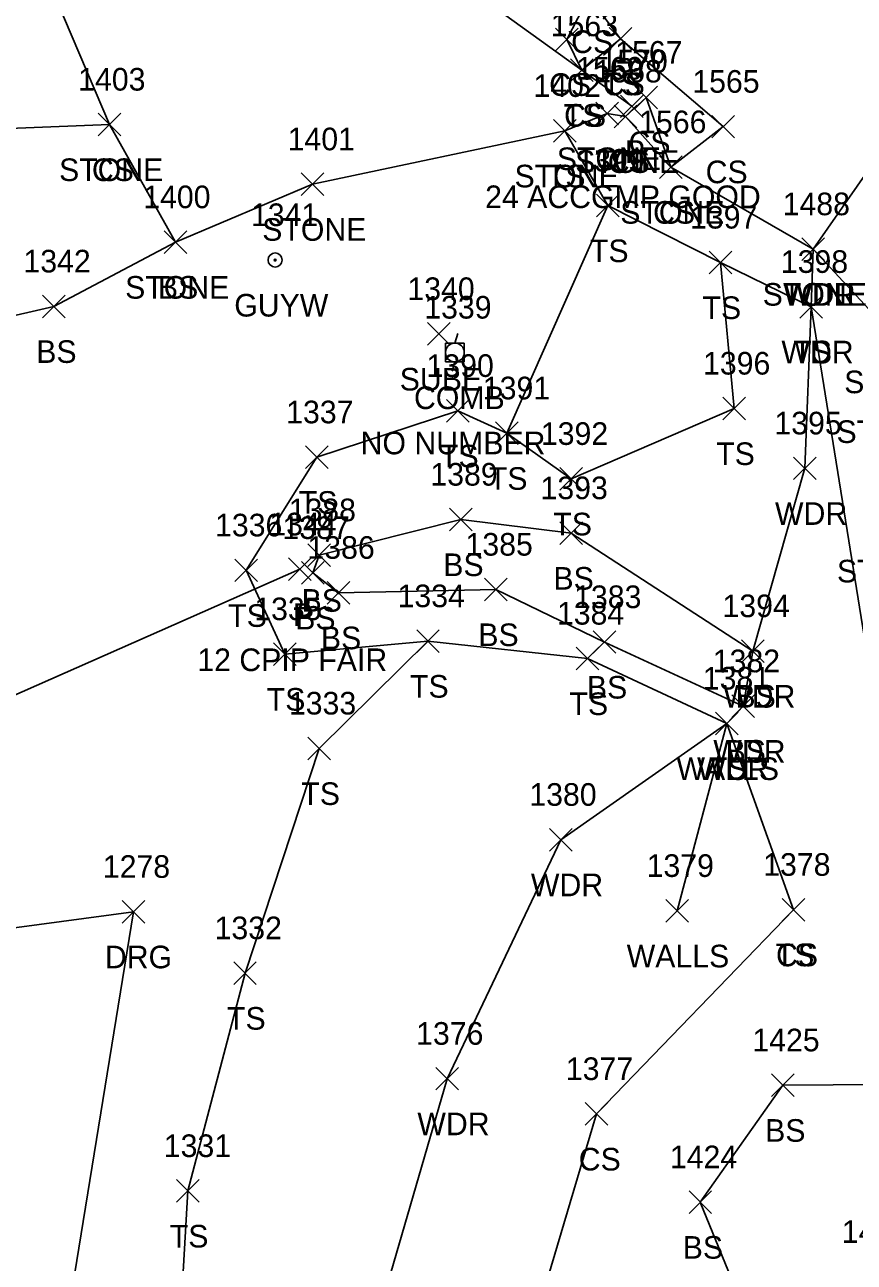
# Model space of a CAD drawing. Extents: x 49137 to 50946, y 9590 to 10709.
# Drawn here: x 50061.8 to 50135.2, y 9888.9 to 9998.3 of the extents above; entities that cross this region are included whole.
import ezdxf

# ---------------------------------------------------------------- set-up
doc = ezdxf.new("R2010")
doc.units = 0
for name, color, linetype in [('D_A', 7, 'Continuous'), ('D_C', 7, 'Continuous'), ('D_I', 7, 'Continuous'), ('D_TIC', 7, 'Continuous'), ('DCP', 7, 'Continuous'), ('L_A', 7, 'Continuous'), ('L_I', 7, 'Continuous'), ('L_TIC', 7, 'Continuous'), ('LASF', 7, 'Continuous'), ('LAWA', 7, 'Continuous'), ('LELB', 7, 'Continuous'), ('LWS', 7, 'Continuous'), ('R_A', 7, 'Continuous'), ('R_I', 7, 'Continuous'), ('R_TIC', 7, 'Continuous'), ('RDG', 7, 'Continuous'), ('U_A', 7, 'Continuous'), ('U_C', 7, 'Continuous'), ('U_I', 7, 'Continuous'), ('U_TIC', 7, 'Continuous'), ('UP', 7, 'Continuous'), ('UPGW', 7, 'Continuous')]:
    doc.layers.add(name, color=color, linetype=linetype)

msp = doc.modelspace()

# ---------------------------------------------------------------- linework, layer by layer
at = {"layer": 'D_TIC'}
for points in [[(50114.5, 9990.1), (50116.5, 9992.1)], [(50116.5, 9990.1), (50114.5, 9992.1)], [(50085.13, 9949.16), (50087.13, 9951.16)], [(50087.13, 9949.16), (50085.13, 9951.16)]]:
    msp.add_lwpolyline(points, dxfattribs=at)
at = {"layer": 'DCP'}
for points in [[(50115.5, 9991.1), (50001.78, 10072.94)], [(50052.95, 9935.51), (50086.13, 9950.16)]]:
    msp.add_lwpolyline(points, dxfattribs=at)
at = {"layer": 'L_TIC'}
for points in [[(50108.74, 9996.02), (50110.74, 9998.02)], [(50110.74, 9996.02), (50108.74, 9998.02)], [(50113.49, 9996.08), (50115.49, 9998.08)], [(50115.49, 9996.08), (50113.49, 9998.08)], [(50113.49, 9996.08), (50115.49, 9998.08)], [(50115.49, 9996.08), (50113.49, 9998.08)], [(50110.06, 9993.3), (50112.06, 9995.3)], [(50112.06, 9993.3), (50110.06, 9995.3)], [(50110.06, 9993.3), (50112.06, 9995.3)], [(50112.06, 9993.3), (50110.06, 9995.3)], [(50115.76, 9990.87), (50117.76, 9992.87)], [(50117.76, 9990.87), (50115.76, 9992.87)], [(50112.32, 9989.46), (50114.32, 9991.46)], [(50114.32, 9989.46), (50112.32, 9991.46)], [(50112.32, 9989.46), (50114.32, 9991.46)], [(50114.32, 9989.46), (50112.32, 9991.46)], [(50113.93, 9989.21), (50115.93, 9991.21)], [(50115.93, 9989.21), (50113.93, 9991.21)], [(50113.93, 9989.21), (50115.93, 9991.21)], [(50115.93, 9989.21), (50113.93, 9991.21)], [(50068.31, 9988.49), (50070.31, 9990.49)], [(50070.31, 9988.49), (50068.31, 9990.49)], [(50068.31, 9988.49), (50070.31, 9990.49)], [(50070.31, 9988.49), (50068.31, 9990.49)], [(50108.58, 9987.93), (50110.58, 9989.93)], [(50110.58, 9987.93), (50108.58, 9989.93)], [(50108.58, 9987.93), (50110.58, 9989.93)], [(50110.58, 9987.93), (50108.58, 9989.93)], [(50122.58, 9988.3), (50124.58, 9990.3)], [(50124.58, 9988.3), (50122.58, 9990.3)], [(50117.93, 9984.72), (50119.93, 9986.72)], [(50119.93, 9984.72), (50117.93, 9986.72)], [(50117.93, 9984.72), (50119.93, 9986.72)], [(50119.93, 9984.72), (50117.93, 9986.72)], [(50086.27, 9983.21), (50088.27, 9985.21)], [(50088.27, 9983.21), (50086.27, 9985.21)], [(50112.38, 9981.32), (50114.38, 9983.32)], [(50114.38, 9981.32), (50112.38, 9983.32)], [(50112.38, 9981.32), (50114.38, 9983.32)], [(50114.38, 9981.32), (50112.38, 9983.32)], [(50074.14, 9978.09), (50076.14, 9980.09)], [(50076.14, 9978.09), (50074.14, 9980.09)], [(50074.14, 9978.09), (50076.14, 9980.09)], [(50076.14, 9978.09), (50074.14, 9980.09)], [(50074.14, 9978.09), (50076.14, 9980.09)], [(50076.14, 9978.09), (50074.14, 9980.09)], [(50130.52, 9977.47), (50132.52, 9979.47)], [(50132.52, 9977.47), (50130.52, 9979.47)], [(50130.52, 9977.47), (50132.52, 9979.47)], [(50132.52, 9977.47), (50130.52, 9979.47)], [(50130.52, 9977.47), (50132.52, 9979.47)], [(50132.52, 9977.47), (50130.52, 9979.47)], [(50122.33, 9976.29), (50124.33, 9978.29)], [(50124.33, 9976.29), (50122.33, 9978.29)], [(50122.33, 9976.29), (50124.33, 9978.29)], [(50124.33, 9976.29), (50122.33, 9978.29)], [(50063.39, 9972.41), (50065.39, 9974.41)], [(50065.39, 9972.41), (50063.39, 9974.41)], [(50130.36, 9972.37), (50132.36, 9974.37)], [(50132.36, 9972.37), (50130.36, 9974.37)], [(50130.36, 9972.37), (50132.36, 9974.37)], [(50132.36, 9972.37), (50130.36, 9974.37)], [(50123.54, 9963.38), (50125.54, 9965.38)], [(50125.54, 9963.38), (50123.54, 9965.38)], [(50099.12, 9963.17), (50101.12, 9965.17)], [(50101.12, 9963.17), (50099.12, 9965.17)], [(50103.44, 9961.19), (50105.44, 9963.19)], [(50105.44, 9961.19), (50103.44, 9963.19)], [(50103.44, 9961.19), (50105.44, 9963.19)], [(50105.44, 9961.19), (50103.44, 9963.19)], [(50086.63, 9959.07), (50088.63, 9961.07)], [(50088.63, 9959.07), (50086.63, 9961.07)], [(50129.79, 9958.09), (50131.79, 9960.09)], [(50131.79, 9958.09), (50129.79, 9960.09)], [(50109.14, 9957.16), (50111.14, 9959.16)], [(50111.14, 9957.16), (50109.14, 9959.16)], [(50099.38, 9953.56), (50101.38, 9955.56)], [(50101.38, 9953.56), (50099.38, 9955.56)], [(50109.12, 9952.36), (50111.12, 9954.36)], [(50111.12, 9952.36), (50109.12, 9954.36)], [(50086.84, 9950.41), (50088.84, 9952.41)], [(50088.84, 9950.41), (50086.84, 9952.41)], [(50080.39, 9949.07), (50082.39, 9951.07)], [(50082.39, 9949.07), (50080.39, 9951.07)], [(50086.29, 9948.84), (50088.29, 9950.84)], [(50088.29, 9948.84), (50086.29, 9950.84)], [(50088.56, 9947.09), (50090.56, 9949.09)], [(50090.56, 9947.09), (50088.56, 9949.09)], [(50102.48, 9947.37), (50104.48, 9949.37)], [(50104.48, 9947.37), (50102.48, 9949.37)], [(50096.47, 9942.81), (50098.47, 9944.81)], [(50098.47, 9942.81), (50096.47, 9944.81)], [(50096.47, 9942.81), (50098.47, 9944.81)], [(50098.47, 9942.81), (50096.47, 9944.81)], [(50112.08, 9942.73), (50114.08, 9944.73)], [(50114.08, 9942.73), (50112.08, 9944.73)], [(50083.8, 9941.66), (50085.8, 9943.66)], [(50085.8, 9941.66), (50083.8, 9943.66)], [(50125.2, 9941.93), (50127.2, 9943.93)], [(50127.2, 9941.93), (50125.2, 9943.93)], [(50125.2, 9941.93), (50127.2, 9943.93)], [(50127.2, 9941.93), (50125.2, 9943.93)], [(50110.57, 9941.27), (50112.57, 9943.27)], [(50112.57, 9941.27), (50110.57, 9943.27)], [(50110.57, 9941.27), (50112.57, 9943.27)], [(50112.57, 9941.27), (50110.57, 9943.27)], [(50124.34, 9937.06), (50126.34, 9939.06)], [(50126.34, 9937.06), (50124.34, 9939.06)], [(50124.34, 9937.06), (50126.34, 9939.06)], [(50126.34, 9937.06), (50124.34, 9939.06)], [(50124.34, 9937.06), (50126.34, 9939.06)], [(50126.34, 9937.06), (50124.34, 9939.06)], [(50122.9, 9935.53), (50124.9, 9937.53)], [(50124.9, 9935.53), (50122.9, 9937.53)], [(50122.9, 9935.53), (50124.9, 9937.53)], [(50124.9, 9935.53), (50122.9, 9937.53)], [(50122.9, 9935.53), (50124.9, 9937.53)], [(50124.9, 9935.53), (50122.9, 9937.53)], [(50086.86, 9933.32), (50088.86, 9935.32)], [(50088.86, 9933.32), (50086.86, 9935.32)], [(50108.21, 9925.25), (50110.21, 9927.25)], [(50110.21, 9925.25), (50108.21, 9927.25)], [(50118.5, 9918.96), (50120.5, 9920.96)], [(50120.5, 9918.96), (50118.5, 9920.96)], [(50128.8, 9919.06), (50130.8, 9921.06)], [(50130.8, 9919.06), (50128.8, 9921.06)], [(50128.8, 9919.06), (50130.8, 9921.06)], [(50130.8, 9919.06), (50128.8, 9921.06)], [(50080.29, 9913.45), (50082.29, 9915.45)], [(50082.29, 9913.45), (50080.29, 9915.45)], [(50098.17, 9904.12), (50100.17, 9906.12)], [(50100.17, 9904.12), (50098.17, 9906.12)], [(50127.84, 9903.54), (50129.84, 9905.54)], [(50129.84, 9903.54), (50127.84, 9905.54)], [(50111.36, 9901), (50113.36, 9903)], [(50113.36, 9901), (50111.36, 9903)], [(50075.24, 9894.19), (50077.24, 9896.19)], [(50077.24, 9894.19), (50075.24, 9896.19)], [(50120.55, 9893.2), (50122.55, 9895.2)], [(50122.55, 9893.2), (50120.55, 9895.2)]]:
    msp.add_lwpolyline(points, dxfattribs=at)
at = {"layer": 'LASF'}
for points in [[(50075.14, 9979.09), (50069.31, 9989.49), (50063.31, 10003.63), (50083.24, 10011.13), (50103.65, 10019.31), (50102.01, 10030.98), (50101.92, 10032.21), (50138.71, 10039.2), (50167.18, 10043.25), (50204.29, 10047.45), (50211.93, 10047.79)], [(50075.14, 9979.09), (50087.27, 9984.21), (50109.58, 9988.93), (50113.32, 9990.46)], [(50138.73, 9970.73), (50131.52, 9978.47), (50118.93, 9985.72), (50114.93, 9990.21), (50113.32, 9990.46)]]:
    msp.add_lwpolyline(points, dxfattribs=at)
at = {"layer": 'LAWA'}
for points in [[(50117.09, 9812.03), (50125.19, 9838.2), (50131.44, 9869.96), (50136.76, 9887.6), (50137.75, 9904.59), (50153.56, 9910.03), (50161.77, 9913.05), (50163.42, 9912.91), (50169.87, 9921.06), (50171.08, 9921.49), (50182.45, 9921.95), (50191.92, 9928.44), (50180.6, 9949.5), (50171.66, 9967.48), (50163.03, 9983.02), (50150.28, 9995.84), (50140.4, 9991.18), (50131.52, 9978.47)], [(50087.28, 9825.27), (50104.34, 9875.01), (50091.4, 9878.44), (50099.17, 9905.12), (50109.21, 9926.25), (50123.9, 9936.53), (50125.34, 9938.06), (50126.2, 9942.93), (50130.79, 9959.09), (50131.36, 9973.37), (50131.52, 9978.47)]]:
    msp.add_lwpolyline(points, dxfattribs=at)
at = {"layer": 'LELB'}
for points in [[(50169.79, 10016.59), (50158.07, 10017.55), (50134.2, 10015.38), (50121.06, 10010.21), (50111.69, 10000.81), (50109.74, 9997.02), (50111.06, 9994.3)], [(50111.69, 10000.81), (50114.49, 9997.08), (50123.58, 9989.3), (50118.93, 9985.72), (50116.76, 9991.87), (50114.93, 9990.21)], [(50111.06, 9994.3), (50114.49, 9997.08)], [(50009.01, 9981.46), (50023.42, 9984.83), (50036.73, 9988.18), (50069.31, 9989.49)], [(50097.47, 9943.81), (50084.8, 9942.66), (50081.39, 9950.07), (50087.63, 9960.07), (50100.12, 9964.17), (50104.44, 9962.19), (50110.14, 9958.16), (50124.54, 9964.38), (50123.33, 9977.29), (50113.38, 9982.32), (50109.58, 9988.93)], [(50104.44, 9962.19), (50113.38, 9982.32)], [(50020.08, 9960.51), (50033.19, 9962.27), (50048.99, 9969.85), (50064.39, 9973.41), (50075.14, 9979.09)], [(50123.33, 9977.29), (50131.36, 9973.37), (50138.53, 9928.68)], [(50125.34, 9938.06), (50113.08, 9943.73), (50103.48, 9948.37), (50089.56, 9948.09), (50087.29, 9949.84), (50087.84, 9951.41), (50100.38, 9954.56), (50110.12, 9953.36), (50126.2, 9942.93)], [(50065.75, 9834.39), (50074.91, 9872.14), (50076.24, 9895.19), (50081.29, 9914.45), (50087.86, 9934.32), (50097.47, 9943.81), (50111.57, 9942.27)], [(50129.8, 9920.06), (50123.9, 9936.53), (50111.57, 9942.27)], [(50131.44, 9869.96), (50121.55, 9894.2), (50128.84, 9904.54), (50137.75, 9904.59), (50140.3, 9923.19), (50138.53, 9928.68), (50138.54, 9928.9), (50144, 9935.71)], [(50104.34, 9875.01), (50112.36, 9902), (50129.8, 9920.06)]]:
    msp.add_lwpolyline(points, dxfattribs=at)
at = {"layer": 'LWS'}
msp.add_lwpolyline([(50119.5, 9919.96), (50123.9, 9936.53)], dxfattribs=at)
at = {"layer": 'R_TIC'}
for points in [[(50070.42, 9918.88), (50072.42, 9920.88)], [(50072.42, 9918.88), (50070.42, 9920.88)]]:
    msp.add_lwpolyline(points, dxfattribs=at)
at = {"layer": 'RDG'}
msp.add_lwpolyline([(49989.55, 9915.93), (50001.07, 9909.43), (50013.31, 9906.77), (50039.56, 9915.6), (50071.42, 9919.88), (50065.07, 9880.71)], dxfattribs=at)
at = {"layer": 'U_TIC'}
for points in [[(50097.43, 9969.97), (50099.43, 9971.97)], [(50099.43, 9969.97), (50097.43, 9971.97)]]:
    msp.add_lwpolyline(points, dxfattribs=at)
at = {"layer": 'UP'}
for p, q in [((50100.1, 9971), (50099.85, 9970.17)), ((50099.01, 9968.5), (50099.01, 9970.17)), ((50099.01, 9970.17), (50100.68, 9970.17)), ((50100.68, 9970.17), (50100.68, 9968.5)), ((50099.85, 9969.33), (50099.85, 9969.33)), ((50100.68, 9968.5), (50099.01, 9968.5)), ((50099.6, 9967.67), (50099.85, 9968.5))]:
    msp.add_line(p, q, dxfattribs=at)
msp.add_circle((50099.85, 9969.33), 0.833, dxfattribs=at)
at = {"layer": 'UPGW'}
for radius in [0.625, 0.0833]:
    msp.add_circle((50083.95, 9977.51), radius, dxfattribs=at)

# ---------------------------------------------------------------- texts
at = {"layer": 'D_A'}
for p in [(50114.88, 9986.1), (50085.51, 9945.16)]:
    msp.add_text('P', height=2, dxfattribs=at).set_placement(p)
at = {"layer": 'D_C'}
for s, p in [('24 ACCGMP GOOD', (50102.52, 9982.1)), ('12 CPIP FAIR', (50077.07, 9941.16))]:
    msp.add_text(s, height=2, dxfattribs=at).set_placement(p)
at = {"layer": 'D_I'}
for s, p in [('1570', (50112.72, 9994.1)), ('1344', (50083.44, 9953.16))]:
    msp.add_text(s, height=2, dxfattribs=at).set_placement(p)
at = {"layer": 'L_A'}
for s, p in [('CS', (50110.13, 9995.81)), ('CS', (50110.13, 9995.81)), ('CS', (50108.18, 9992.02)), ('TS', (50112.9, 9992.08)), ('CS', (50112.93, 9992.08)), ('TS', (50109.47, 9989.3)), ('CS', (50109.5, 9989.3)), ('CS', (50115.2, 9986.87)), ('STONE', (50108.86, 9985.46)), ('STONE', (50108.86, 9985.46)), ('STONE', (50110.48, 9985.21)), ('CS', (50113.37, 9985.21)), ('STONE', (50064.85, 9984.49)), ('CS', (50067.75, 9984.49)), ('CS', (50122.02, 9984.3)), ('STONE', (50105.12, 9983.93)), ('TS', (50107.98, 9983.93)), ('STONE', (50114.47, 9980.72)), ('CS', (50117.37, 9980.72)), ('STONE', (50082.81, 9979.21)), ('TS', (50111.79, 9977.32)), ('TS', (50111.79, 9977.32)), ('STONE', (50070.69, 9974.09)), ('STONE', (50070.69, 9974.09)), ('BS', (50073.59, 9974.09)), ('STONE', (50127.06, 9973.47)), ('WDR', (50128.88, 9973.47)), ('WDL', (50128.94, 9973.47)), ('TS', (50121.74, 9972.29)), ('TS', (50121.74, 9972.29)), ('BS', (50062.83, 9968.41)), ('WDR', (50128.72, 9968.37)), ('TS', (50129.77, 9968.37)), ('STONE', (50134.27, 9965.73)), ('STONE', (50134.27, 9965.73)), ('STONE', (50133.59, 9961.33)), ('TS', (50098.53, 9959.17)), ('TS', (50122.95, 9959.38)), ('TS', (50102.85, 9957.19)), ('TS', (50102.85, 9957.19)), ('TS', (50086.04, 9955.07)), ('WDR', (50128.15, 9954.09)), ('TS', (50108.55, 9953.16)), ('BS', (50098.82, 9949.56)), ('BS', (50108.56, 9948.36)), ('STONE', (50133.63, 9949)), ('BS', (50086.29, 9946.41)), ('TS', (50079.8, 9945.07)), ('BS', (50085.73, 9944.84)), ('BS', (50088, 9943.09)), ('BS', (50101.92, 9943.37)), ('TS', (50095.88, 9938.81)), ('TS', (50095.88, 9938.81)), ('BS', (50111.52, 9938.73)), ('TS', (50083.21, 9937.66)), ('TS', (50109.98, 9937.27)), ('TS', (50109.98, 9937.27)), ('WDR', (50123.57, 9937.93)), ('BS', (50124.65, 9937.93)), ('WDR', (50122.7, 9933.06)), ('BS', (50123.78, 9933.06)), ('BS', (50123.78, 9933.06)), ('WALLS', (50119.44, 9931.53)), ('WDR', (50121.26, 9931.53)), ('TS', (50122.31, 9931.53)), ('TS', (50086.27, 9929.32)), ('WDR', (50106.57, 9921.25)), ('WALLS', (50115.04, 9914.96)), ('TS', (50128.21, 9915.06)), ('CS', (50128.24, 9915.06)), ('TS', (50079.7, 9909.45)), ('WDR', (50096.53, 9900.12)), ('BS', (50127.28, 9899.54)), ('CS', (50110.8, 9897)), ('TS', (50074.64, 9890.19)), ('BS', (50119.99, 9889.2))]:
    msp.add_text(s, height=2, dxfattribs=at).set_placement(p)
at = {"layer": 'L_I'}
for s, p in [('1563', (50108.32, 9997.3)), ('1563', (50108.32, 9997.3)), ('1567', (50114.02, 9994.87)), ('1569', (50110.57, 9993.46)), ('1569', (50110.57, 9993.46)), ('1568', (50112.19, 9993.21)), ('1568', (50112.19, 9993.21)), ('1403', (50066.54, 9992.49)), ('1403', (50066.54, 9992.49)), ('1402', (50106.8, 9991.93)), ('1402', (50106.8, 9991.93)), ('1565', (50120.84, 9992.3)), ('1566', (50116.14, 9988.72)), ('1566', (50116.14, 9988.72)), ('1401', (50085.06, 9987.21)), ('1399', (50110.68, 9985.32)), ('1399', (50110.68, 9985.32)), ('1400', (50072.29, 9982.09)), ('1400', (50072.29, 9982.09)), ('1400', (50072.29, 9982.09)), ('1488', (50128.83, 9981.47)), ('1488', (50128.83, 9981.47)), ('1488', (50128.83, 9981.47)), ('1397', (50120.64, 9980.29)), ('1397', (50120.64, 9980.29)), ('1342', (50061.7, 9976.41)), ('1398', (50128.67, 9976.37)), ('1398', (50128.67, 9976.37)), ('1390', (50097.34, 9967.17)), ('1396', (50121.79, 9967.38)), ('1391', (50102.32, 9965.19)), ('1391', (50102.32, 9965.19)), ('1337', (50084.93, 9963.07)), ('1392', (50107.45, 9961.16)), ('1395', (50128.1, 9962.09)), ('1389', (50097.68, 9957.56)), ('1393', (50107.42, 9956.36)), ('1388', (50085.15, 9954.41)), ('1336', (50078.64, 9953.07)), ('1387', (50084.6, 9952.84)), ('1385', (50100.79, 9951.37)), ('1386', (50086.81, 9951.09)), ('1334', (50094.78, 9946.81)), ('1334', (50094.78, 9946.81)), ('1383', (50110.39, 9946.73)), ('1394', (50123.51, 9945.93)), ('1394', (50123.51, 9945.93)), ('1335', (50082.11, 9945.66)), ('1384', (50108.87, 9945.27)), ('1384', (50108.87, 9945.27)), ('1382', (50122.65, 9941.06)), ('1382', (50122.65, 9941.06)), ('1382', (50122.65, 9941.06)), ('1381', (50121.77, 9939.53)), ('1381', (50121.77, 9939.53)), ('1381', (50121.77, 9939.53)), ('1333', (50085.17, 9937.32)), ('1380', (50106.43, 9929.25)), ('1379', (50116.8, 9922.96)), ('1378', (50127.11, 9923.06)), ('1378', (50127.11, 9923.06)), ('1332', (50078.6, 9917.45)), ('1376', (50096.42, 9908.12)), ('1425', (50126.15, 9907.54)), ('1377', (50109.66, 9905)), ('1331', (50074.11, 9898.19)), ('1424', (50118.86, 9897.2)), ('1423', (50134.06, 9890.6))]:
    msp.add_text(s, height=2, dxfattribs=at).set_placement(p)
at = {"layer": 'R_A'}
msp.add_text('DRG', height=2, dxfattribs=at).set_placement((50068.9, 9914.88))
at = {"layer": 'R_I'}
msp.add_text('1278', height=2, dxfattribs=at).set_placement((50068.72, 9922.88))
at = {"layer": 'U_A'}
for s, p in [('GUYW', (50080.34, 9972.51)), ('SUBE', (50094.97, 9965.97)), ('COMB', (50096.23, 9964.33))]:
    msp.add_text(s, height=2, dxfattribs=at).set_placement(p)
at = {"layer": 'U_C'}
msp.add_text('NO NUMBER', height=2, dxfattribs=at).set_placement((50091.51, 9960.33))
at = {"layer": 'U_I'}
for s, p in [('1341', (50081.82, 9980.51)), ('1340', (50095.65, 9973.97)), ('1339', (50097.14, 9972.33))]:
    msp.add_text(s, height=2, dxfattribs=at).set_placement(p)

doc.saveas('drawing.dxf')
